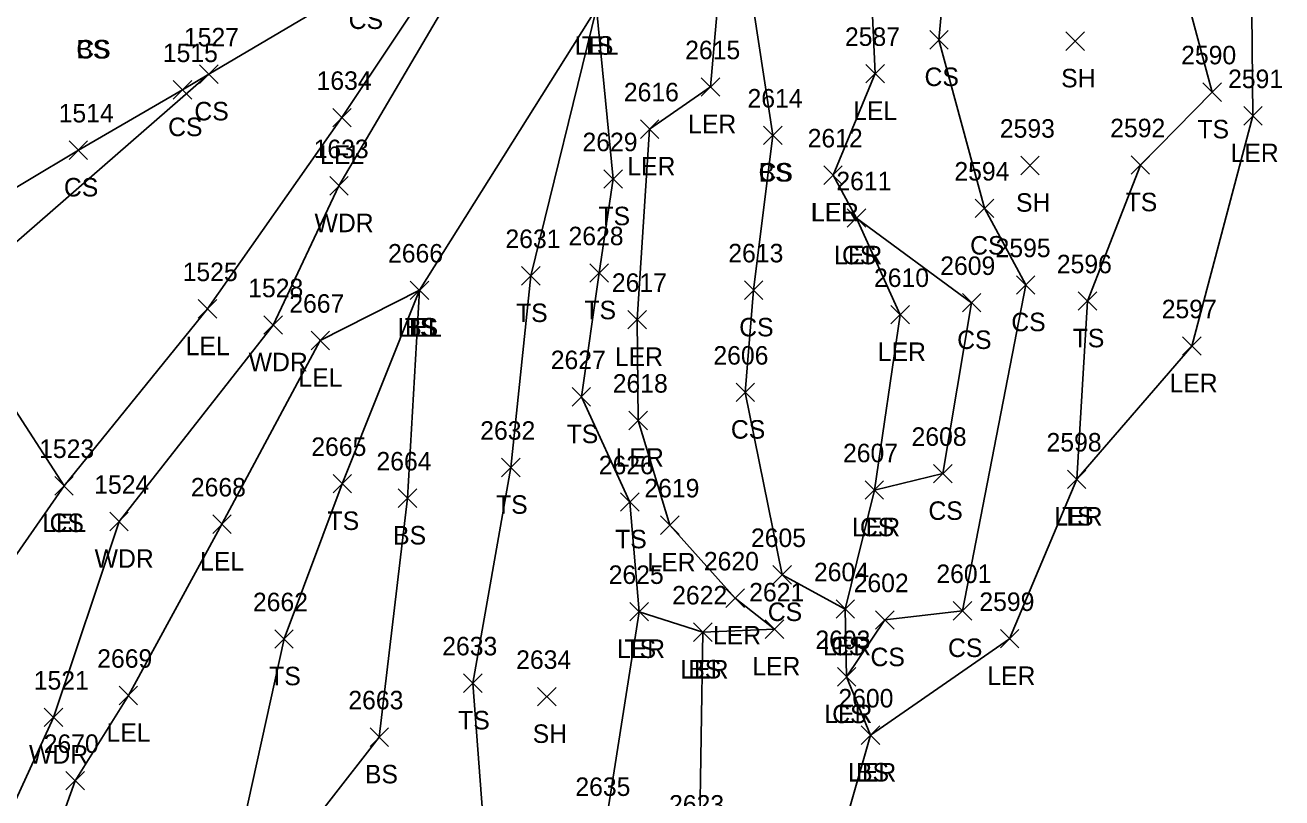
# Model space of a CAD drawing. Extents: x 1483143 to 1488182, y 802902 to 807581.
# Drawn here: x 1487627.8 to 1487763.6, y 805774.4 to 805857.9 of the extents above; entities that cross this region are included whole.
import ezdxf

# ---------------------------------------------------------------- set-up
doc = ezdxf.new("R2010")
doc.units = 0
for name, color, linetype in [('L_A', 7, 'Continuous'), ('L_I', 7, 'Continuous'), ('L_TIC', 7, 'Continuous'), ('LARO', 7, 'Continuous'), ('LAWA', 7, 'Continuous'), ('LELB', 7, 'Continuous')]:
    doc.layers.add(name, color=color, linetype=linetype)

msp = doc.modelspace()

# ---------------------------------------------------------------- linework, layer by layer
at = {"layer": 'L_TIC'}
for points in [[(1487725.58, 805855.28), (1487727.58, 805857.28)], [(1487727.58, 805855.28), (1487725.58, 805857.28)], [(1487740.3, 805855.14), (1487742.3, 805857.14)], [(1487742.3, 805855.14), (1487740.3, 805857.14)], [(1487646.66, 805851.57), (1487648.66, 805853.57)], [(1487648.66, 805851.57), (1487646.66, 805853.57)], [(1487646.66, 805851.57), (1487648.66, 805853.57)], [(1487648.66, 805851.57), (1487646.66, 805853.57)], [(1487718.68, 805851.62), (1487720.68, 805853.62)], [(1487720.68, 805851.62), (1487718.68, 805853.62)], [(1487643.82, 805849.87), (1487645.82, 805851.87)], [(1487645.82, 805849.87), (1487643.82, 805851.87)], [(1487700.89, 805850.18), (1487702.89, 805852.18)], [(1487702.89, 805850.18), (1487700.89, 805852.18)], [(1487755.11, 805849.63), (1487757.11, 805851.63)], [(1487757.11, 805849.63), (1487755.11, 805851.63)], [(1487759.52, 805847.06), (1487761.52, 805849.06)], [(1487761.52, 805847.06), (1487759.52, 805849.06)], [(1487661.05, 805846.87), (1487663.05, 805848.87)], [(1487663.05, 805846.87), (1487661.05, 805848.87)], [(1487694.31, 805845.63), (1487696.31, 805847.63)], [(1487696.31, 805845.63), (1487694.31, 805847.63)], [(1487707.63, 805844.96), (1487709.63, 805846.96)], [(1487709.63, 805844.96), (1487707.63, 805846.96)], [(1487707.63, 805844.96), (1487709.63, 805846.96)], [(1487709.63, 805844.96), (1487707.63, 805846.96)], [(1487632.56, 805843.35), (1487634.56, 805845.35)], [(1487634.56, 805843.35), (1487632.56, 805845.35)], [(1487735.42, 805841.7), (1487737.42, 805843.7)], [(1487737.42, 805841.7), (1487735.42, 805843.7)], [(1487747.35, 805841.75), (1487749.35, 805843.75)], [(1487749.35, 805841.75), (1487747.35, 805843.75)], [(1487690.37, 805840.24), (1487692.37, 805842.24)], [(1487692.37, 805840.24), (1487690.37, 805842.24)], [(1487714.13, 805840.65), (1487716.13, 805842.65)], [(1487716.13, 805840.65), (1487714.13, 805842.65)], [(1487714.13, 805840.65), (1487716.13, 805842.65)], [(1487716.13, 805840.65), (1487714.13, 805842.65)], [(1487660.73, 805839.49), (1487662.73, 805841.49)], [(1487662.73, 805839.49), (1487660.73, 805841.49)], [(1487730.51, 805837.07), (1487732.51, 805839.07)], [(1487732.51, 805837.07), (1487730.51, 805839.07)], [(1487716.66, 805836.02), (1487718.66, 805838.02)], [(1487718.66, 805836.02), (1487716.66, 805838.02)], [(1487716.66, 805836.02), (1487718.66, 805838.02)], [(1487718.66, 805836.02), (1487716.66, 805838.02)], [(1487681.46, 805829.78), (1487683.46, 805831.78)], [(1487683.46, 805829.78), (1487681.46, 805831.78)], [(1487688.85, 805830.08), (1487690.85, 805832.08)], [(1487690.85, 805830.08), (1487688.85, 805832.08)], [(1487669.44, 805828.21), (1487671.44, 805830.21)], [(1487671.44, 805828.21), (1487669.44, 805830.21)], [(1487669.44, 805828.21), (1487671.44, 805830.21)], [(1487671.44, 805828.21), (1487669.44, 805830.21)], [(1487669.44, 805828.21), (1487671.44, 805830.21)], [(1487671.44, 805828.21), (1487669.44, 805830.21)], [(1487705.55, 805828.23), (1487707.55, 805830.23)], [(1487707.55, 805828.23), (1487705.55, 805830.23)], [(1487734.96, 805828.79), (1487736.96, 805830.79)], [(1487736.96, 805828.79), (1487734.96, 805830.79)], [(1487729.11, 805826.87), (1487731.11, 805828.87)], [(1487731.11, 805826.87), (1487729.11, 805828.87)], [(1487741.63, 805827.05), (1487743.63, 805829.05)], [(1487743.63, 805827.05), (1487741.63, 805829.05)], [(1487646.52, 805826.2), (1487648.52, 805828.2)], [(1487648.52, 805826.2), (1487646.52, 805828.2)], [(1487721.39, 805825.57), (1487723.39, 805827.57)], [(1487723.39, 805825.57), (1487721.39, 805827.57)], [(1487653.61, 805824.46), (1487655.61, 805826.46)], [(1487655.61, 805824.46), (1487653.61, 805826.46)], [(1487692.97, 805825.04), (1487694.97, 805827.04)], [(1487694.97, 805825.04), (1487692.97, 805827.04)], [(1487658.71, 805822.79), (1487660.71, 805824.79)], [(1487660.71, 805822.79), (1487658.71, 805824.79)], [(1487752.92, 805822.19), (1487754.92, 805824.19)], [(1487754.92, 805822.19), (1487752.92, 805824.19)], [(1487704.65, 805817.18), (1487706.65, 805819.18)], [(1487706.65, 805817.18), (1487704.65, 805819.18)], [(1487686.93, 805816.69), (1487688.93, 805818.69)], [(1487688.93, 805816.69), (1487686.93, 805818.69)], [(1487693.06, 805814.15), (1487695.06, 805816.15)], [(1487695.06, 805814.15), (1487693.06, 805816.15)], [(1487679.31, 805809.06), (1487681.31, 805811.06)], [(1487681.31, 805809.06), (1487679.31, 805811.06)], [(1487726, 805808.4), (1487728, 805810.4)], [(1487728, 805808.4), (1487726, 805810.4)], [(1487740.47, 805807.79), (1487742.47, 805809.79)], [(1487742.47, 805807.79), (1487740.47, 805809.79)], [(1487740.47, 805807.79), (1487742.47, 805809.79)], [(1487742.47, 805807.79), (1487740.47, 805809.79)], [(1487631.01, 805807.09), (1487633.01, 805809.09)], [(1487633.01, 805807.09), (1487631.01, 805809.09)], [(1487631.01, 805807.09), (1487633.01, 805809.09)], [(1487633.01, 805807.09), (1487631.01, 805809.09)], [(1487661.09, 805807.31), (1487663.09, 805809.31)], [(1487663.09, 805807.31), (1487661.09, 805809.31)], [(1487718.6, 805806.63), (1487720.6, 805808.63)], [(1487720.6, 805806.63), (1487718.6, 805808.63)], [(1487718.6, 805806.63), (1487720.6, 805808.63)], [(1487720.6, 805806.63), (1487718.6, 805808.63)], [(1487668.14, 805805.74), (1487670.14, 805807.74)], [(1487670.14, 805805.74), (1487668.14, 805807.74)], [(1487692.17, 805805.33), (1487694.17, 805807.33)], [(1487694.17, 805805.33), (1487692.17, 805807.33)], [(1487636.96, 805803.22), (1487638.96, 805805.22)], [(1487638.96, 805803.22), (1487636.96, 805805.22)], [(1487648.08, 805802.93), (1487650.08, 805804.93)], [(1487650.08, 805802.93), (1487648.08, 805804.93)], [(1487696.49, 805802.83), (1487698.49, 805804.83)], [(1487698.49, 805802.83), (1487696.49, 805804.83)], [(1487708.64, 805797.47), (1487710.64, 805799.47)], [(1487710.64, 805797.47), (1487708.64, 805799.47)], [(1487703.56, 805794.94), (1487705.56, 805796.94)], [(1487705.56, 805794.94), (1487703.56, 805796.94)], [(1487693.18, 805793.48), (1487695.18, 805795.48)], [(1487695.18, 805793.48), (1487693.18, 805795.48)], [(1487693.18, 805793.48), (1487695.18, 805795.48)], [(1487695.18, 805793.48), (1487693.18, 805795.48)], [(1487715.46, 805793.77), (1487717.46, 805795.77)], [(1487717.46, 805793.77), (1487715.46, 805795.77)], [(1487715.46, 805793.77), (1487717.46, 805795.77)], [(1487717.46, 805793.77), (1487715.46, 805795.77)], [(1487719.74, 805792.59), (1487721.74, 805794.59)], [(1487721.74, 805792.59), (1487719.74, 805794.59)], [(1487728.12, 805793.58), (1487730.12, 805795.58)], [(1487730.12, 805793.58), (1487728.12, 805795.58)], [(1487700.05, 805791.26), (1487702.05, 805793.26)], [(1487702.05, 805791.26), (1487700.05, 805793.26)], [(1487700.05, 805791.26), (1487702.05, 805793.26)], [(1487702.05, 805791.26), (1487700.05, 805793.26)], [(1487707.81, 805791.59), (1487709.81, 805793.59)], [(1487709.81, 805791.59), (1487707.81, 805793.59)], [(1487654.79, 805790.53), (1487656.79, 805792.53)], [(1487656.79, 805790.53), (1487654.79, 805792.53)], [(1487733.22, 805790.56), (1487735.22, 805792.56)], [(1487735.22, 805790.56), (1487733.22, 805792.56)], [(1487715.6, 805786.44), (1487717.6, 805788.44)], [(1487717.6, 805786.44), (1487715.6, 805788.44)], [(1487715.6, 805786.44), (1487717.6, 805788.44)], [(1487717.6, 805786.44), (1487715.6, 805788.44)], [(1487675.2, 805785.76), (1487677.2, 805787.76)], [(1487677.2, 805785.76), (1487675.2, 805787.76)], [(1487637.97, 805784.42), (1487639.97, 805786.42)], [(1487639.97, 805784.42), (1487637.97, 805786.42)], [(1487683.19, 805784.3), (1487685.19, 805786.3)], [(1487685.19, 805784.3), (1487683.19, 805786.3)], [(1487629.87, 805782.06), (1487631.87, 805784.06)], [(1487631.87, 805782.06), (1487629.87, 805784.06)], [(1487665.09, 805779.93), (1487667.09, 805781.93)], [(1487667.09, 805779.93), (1487665.09, 805781.93)], [(1487718.18, 805780.13), (1487720.18, 805782.13)], [(1487720.18, 805780.13), (1487718.18, 805782.13)], [(1487718.18, 805780.13), (1487720.18, 805782.13)], [(1487720.18, 805780.13), (1487718.18, 805782.13)], [(1487632.21, 805775.22), (1487634.21, 805777.22)], [(1487634.21, 805775.22), (1487632.21, 805777.22)]]:
    msp.add_lwpolyline(points, dxfattribs=at)
at = {"layer": 'LARO'}
for points in [[(1487519.52, 805604.85), (1487528.65, 805619.18), (1487533.33, 805631.91), (1487543.2, 805654.53), (1487555.05, 805678.36), (1487574.29, 805702.91), (1487587.86, 805730.92), (1487594.38, 805745.99), (1487602.81, 805747.66), (1487615.34, 805754.21), (1487619.89, 805765.57), (1487618.06, 805788.02), (1487632.01, 805808.09), (1487647.52, 805827.2), (1487662.05, 805847.87), (1487673.84, 805865.59), (1487680.96, 805879.63), (1487690.31, 805890.08), (1487695.82, 805899.7), (1487708.05, 805917.66), (1487714.11, 805946.66), (1487707.45, 805965.6), (1487711.43, 805989.94)], [(1487752.15, 805961.27), (1487748.72, 805973.01), (1487741.47, 805961.54), (1487740.15, 805943.19), (1487733.63, 805923.95), (1487737.11, 805900.7), (1487723.44, 805897.38), (1487717.22, 805893.09), (1487718.72, 805873.74), (1487719.68, 805852.62), (1487715.13, 805841.65)], [(1487755.61, 805957.28), (1487750, 805935.31), (1487743.18, 805906.03), (1487753.64, 805891.61), (1487760.17, 805881.7), (1487760.52, 805848.06), (1487753.92, 805823.19), (1487741.47, 805808.79), (1487734.22, 805791.56), (1487719.18, 805781.13), (1487716.6, 805787.44), (1487716.46, 805794.77), (1487719.6, 805807.63), (1487722.39, 805826.57), (1487717.66, 805837.02), (1487715.13, 805841.65)], [(1487705.29, 805896.34), (1487695.87, 805891.2), (1487689.13, 805878.29), (1487689.57, 805859.67), (1487670.44, 805829.21), (1487659.71, 805823.79), (1487649.08, 805803.93), (1487638.97, 805785.42), (1487633.21, 805776.22), (1487626.14, 805756.53), (1487619.37, 805736.85), (1487617.73, 805704.95), (1487625.22, 805691.16), (1487634.64, 805682.02), (1487622.34, 805673.38), (1487621.2, 805638.86), (1487621.06, 805617.78)], [(1487705.29, 805896.34), (1487704.06, 805875.92), (1487701.89, 805851.18), (1487695.31, 805846.63), (1487693.97, 805826.04), (1487694.06, 805815.15), (1487697.49, 805803.83), (1487704.56, 805795.94), (1487708.81, 805792.59), (1487701.05, 805792.26), (1487694.18, 805794.48), (1487690.59, 805771.57), (1487689.27, 805761.59), (1487692.86, 805752.01), (1487698.86, 805745.28), (1487699.02, 805718.81), (1487691.81, 805707.17), (1487691.68, 805697.79), (1487684.12, 805691.56), (1487666.83, 805689.24), (1487654.3, 805698.63), (1487654.93, 805715.83), (1487638.67, 805718.86)]]:
    msp.add_lwpolyline(points, dxfattribs=at)
at = {"layer": 'LAWA'}
msp.add_lwpolyline([(1487529.09, 805606.14), (1487539.28, 805632.42), (1487550.45, 805657.72), (1487555.05, 805678.36), (1487580.53, 805701.65), (1487594.42, 805727.14), (1487615.34, 805754.21), (1487623.26, 805766.5), (1487630.87, 805783.06), (1487637.96, 805804.22), (1487654.61, 805825.46), (1487661.73, 805840.49), (1487675.69, 805864.29), (1487683.26, 805876.52), (1487690.31, 805890.08), (1487698.57, 805894.98), (1487712.71, 805915.11), (1487715.76, 805935.97), (1487722.85, 805947.47), (1487721.66, 805955.35), (1487715.74, 805966.94), (1487726.15, 805982.46)], dxfattribs=at)
at = {"layer": 'LELB'}
for points in [[(1487632.01, 805808.09), (1487619.24, 805827.81), (1487647.66, 805852.57), (1487664.34, 805862.45), (1487671.06, 805867.81), (1487675.43, 805874.85), (1487684.3, 805891.3), (1487690.96, 805911.62), (1487700.16, 805920.88), (1487706.33, 805937.53), (1487707.55, 805950.23), (1487702.79, 805967.14), (1487703.8, 805992.98), (1487705.2, 806012.67), (1487721.31, 806024.08), (1487727.61, 806022.94), (1487740.06, 806020.89), (1487749.42, 806025.91)], [(1487753.64, 805891.61), (1487729.47, 805887.69), (1487726.58, 805856.28), (1487731.51, 805838.07), (1487735.96, 805829.79), (1487729.12, 805794.58), (1487720.74, 805793.59), (1487716.6, 805787.44)], [(1487753.64, 805891.61), (1487748.81, 805877.84), (1487756.11, 805850.63), (1487748.35, 805842.75), (1487742.63, 805828.05), (1487741.47, 805808.79)], [(1487704.06, 805875.92), (1487708.63, 805845.96)], [(1487694.18, 805794.48), (1487693.17, 805806.33), (1487687.93, 805817.69), (1487689.85, 805831.08), (1487691.37, 805841.24), (1487689.57, 805859.67), (1487682.46, 805830.78), (1487680.31, 805810.06), (1487676.2, 805786.76), (1487678.62, 805754.73), (1487686.02, 805754.18), (1487689.27, 805761.59)], [(1487578.75, 805774.48), (1487581.97, 805774.39), (1487587.14, 805787.59), (1487593.1, 805801.28), (1487606.99, 805818.57), (1487613.06, 805830.36), (1487622.23, 805837.57), (1487633.56, 805844.35), (1487644.82, 805850.87), (1487647.66, 805852.57)], [(1487716.46, 805794.77), (1487709.64, 805798.47), (1487705.65, 805818.18), (1487706.55, 805829.23), (1487708.63, 805845.96)], [(1487719.6, 805807.63), (1487727, 805809.4), (1487730.11, 805827.87), (1487717.66, 805837.02)], [(1487638.67, 805718.86), (1487643.52, 805738.7), (1487650.9, 805769.31), (1487655.79, 805791.53), (1487662.09, 805808.31), (1487670.44, 805829.21)], [(1487701.05, 805792.26), (1487700.71, 805769.66), (1487692.86, 805752.01), (1487679.23, 805741.52), (1487664.55, 805736.58), (1487656.42, 805737.45), (1487655.2, 805766.96), (1487666.09, 805780.93), (1487669.14, 805806.74), (1487670.44, 805829.21)], [(1487719.18, 805781.13), (1487710.75, 805751.72)]]:
    msp.add_lwpolyline(points, dxfattribs=at)

# ---------------------------------------------------------------- texts
at = {"layer": 'L_A'}
for s, p in [('CS', (1487662.78, 805857.45)), ('CS', (1487633.34, 805854.26)), ('BS', (1487633.34, 805854.26)), ('LEL', (1487687.2, 805854.67)), ('TS', (1487687.97, 805854.67)), ('CS', (1487725.02, 805851.28)), ('SH', (1487739.79, 805851.14)), ('CS', (1487646.1, 805847.57)), ('CS', (1487646.1, 805847.57)), ('LEL', (1487717.31, 805847.62)), ('CS', (1487643.26, 805845.87)), ('LER', (1487699.47, 805846.18)), ('TS', (1487754.52, 805845.63)), ('LEL', (1487659.69, 805842.87)), ('LER', (1487758.1, 805843.06)), ('LER', (1487692.89, 805841.63)), ('CS', (1487707.08, 805840.96)), ('BS', (1487707.08, 805840.96)), ('CS', (1487632, 805839.35)), ('SH', (1487734.91, 805837.7)), ('TS', (1487746.76, 805837.75)), ('TS', (1487689.78, 805836.24)), ('LER', (1487712.72, 805836.65)), ('LEL', (1487712.77, 805836.65)), ('WDR', (1487659.09, 805835.49)), ('LER', (1487715.25, 805832.02)), ('CS', (1487716.1, 805832.02)), ('CS', (1487729.95, 805833.07)), ('TS', (1487680.87, 805825.78)), ('TS', (1487688.26, 805826.08)), ('LEL', (1487668.07, 805824.21)), ('TS', (1487668.84, 805824.21)), ('BS', (1487668.88, 805824.21)), ('CS', (1487704.99, 805824.23)), ('CS', (1487734.4, 805824.79)), ('CS', (1487728.55, 805822.87)), ('TS', (1487741.04, 805823.05)), ('LEL', (1487645.16, 805822.2)), ('LER', (1487719.97, 805821.57)), ('WDR', (1487651.97, 805820.46)), ('LER', (1487691.55, 805821.04)), ('LEL', (1487657.35, 805818.79)), ('LER', (1487751.5, 805818.19)), ('CS', (1487704.09, 805813.18)), ('TS', (1487686.34, 805812.69)), ('LER', (1487691.64, 805810.15)), ('TS', (1487678.71, 805805.06)), ('CS', (1487725.44, 805804.4)), ('LER', (1487739.05, 805803.79)), ('TS', (1487739.88, 805803.79)), ('LEL', (1487629.65, 805803.09)), ('CS', (1487630.45, 805803.09)), ('TS', (1487660.5, 805803.31)), ('LER', (1487717.18, 805802.63)), ('CS', (1487718.04, 805802.63)), ('BS', (1487667.58, 805801.74)), ('TS', (1487691.58, 805801.33)), ('WDR', (1487635.32, 805799.22)), ('LEL', (1487646.72, 805798.93)), ('LER', (1487695.07, 805798.83)), ('CS', (1487708.08, 805793.47)), ('LER', (1487702.15, 805790.94)), ('LER', (1487691.77, 805789.48)), ('TS', (1487692.59, 805789.48)), ('LER', (1487714.04, 805789.77)), ('CS', (1487714.9, 805789.77)), ('CS', (1487719.18, 805788.59)), ('CS', (1487727.56, 805789.58)), ('LER', (1487698.63, 805787.26)), ('BS', (1487699.49, 805787.26)), ('LER', (1487706.4, 805787.59)), ('TS', (1487654.19, 805786.53)), ('LER', (1487731.8, 805786.56)), ('TS', (1487674.61, 805781.76)), ('LER', (1487714.18, 805782.44)), ('CS', (1487715.04, 805782.44)), ('LEL', (1487636.6, 805780.42)), ('SH', (1487682.67, 805780.3)), ('WDR', (1487628.23, 805778.06)), ('BS', (1487664.54, 805775.93)), ('LER', (1487716.76, 805776.13)), ('BS', (1487717.62, 805776.13))]:
    msp.add_text(s, height=2, dxfattribs=at).set_placement(p)
at = {"layer": 'L_I'}
for s, p in [('1527', (1487644.97, 805855.57)), ('1527', (1487644.97, 805855.57)), ('2587', (1487716.42, 805855.62)), ('1515', (1487642.69, 805853.87)), ('2615', (1487699.15, 805854.18)), ('2590', (1487752.76, 805853.63)), ('2591', (1487757.83, 805851.06)), ('1634', (1487659.31, 805850.87)), ('2616', (1487692.52, 805849.63)), ('2614', (1487705.89, 805848.96)), ('2614', (1487705.89, 805848.96)), ('1514', (1487631.43, 805847.35)), ('2593', (1487733.16, 805845.7)), ('2592', (1487745.09, 805845.75)), ('2629', (1487688.05, 805844.24)), ('2612', (1487712.39, 805844.65)), ('2612', (1487712.39, 805844.65)), ('1633', (1487658.99, 805843.49)), ('2594', (1487728.25, 805841.07)), ('2611', (1487715.49, 805840.02)), ('2611', (1487715.49, 805840.02)), ('2631', (1487679.72, 805833.78)), ('2628', (1487686.54, 805834.08)), ('2666', (1487667.03, 805832.21)), ('2666', (1487667.03, 805832.21)), ('2666', (1487667.03, 805832.21)), ('2613', (1487703.81, 805832.23)), ('2595', (1487732.7, 805832.79)), ('2609', (1487726.72, 805830.87)), ('2596', (1487739.32, 805831.05)), ('1525', (1487644.83, 805830.2)), ('2610', (1487719.56, 805829.57)), ('1528', (1487651.92, 805828.46)), ('2617', (1487691.23, 805829.04)), ('2667', (1487656.36, 805826.79)), ('2597', (1487750.66, 805826.19)), ('2606', (1487702.2, 805821.18)), ('2627', (1487684.62, 805820.69)), ('2618', (1487691.32, 805818.15)), ('2632', (1487677, 805813.06)), ('2608', (1487723.62, 805812.4)), ('2598', (1487738.21, 805811.79)), ('2598', (1487738.21, 805811.79)), ('1523', (1487629.32, 805811.09)), ('1523', (1487629.32, 805811.09)), ('2665', (1487658.74, 805811.31)), ('2607', (1487716.21, 805810.63)), ('2607', (1487716.21, 805810.63)), ('2664', (1487665.78, 805809.74)), ('2626', (1487689.81, 805809.33)), ('1524', (1487635.27, 805807.22)), ('2668', (1487645.72, 805806.93)), ('2619', (1487694.74, 805806.83)), ('2605', (1487706.26, 805801.47)), ('2620', (1487701.17, 805798.94)), ('2625', (1487690.88, 805797.48)), ('2625', (1487690.88, 805797.48)), ('2604', (1487713.07, 805797.77)), ('2604', (1487713.07, 805797.77)), ('2601', (1487726.3, 805797.58)), ('2621', (1487706.07, 805795.59)), ('2602', (1487717.36, 805796.59)), ('2662', (1487652.43, 805794.53)), ('2622', (1487697.74, 805795.26)), ('2622', (1487697.74, 805795.26)), ('2599', (1487730.95, 805794.56)), ('2603', (1487713.22, 805790.44)), ('2603', (1487713.22, 805790.44)), ('2633', (1487672.89, 805789.76)), ('2669', (1487635.6, 805788.42)), ('2634', (1487680.88, 805788.3)), ('1521', (1487628.74, 805786.06)), ('2663', (1487662.74, 805783.93)), ('2600', (1487715.71, 805784.13)), ('2600', (1487715.71, 805784.13)), ('2670', (1487629.81, 805779.22)), ('2635', (1487687.28, 805774.57)), ('2623', (1487697.41, 805772.66))]:
    msp.add_text(s, height=2, dxfattribs=at).set_placement(p)

doc.saveas('drawing.dxf')
